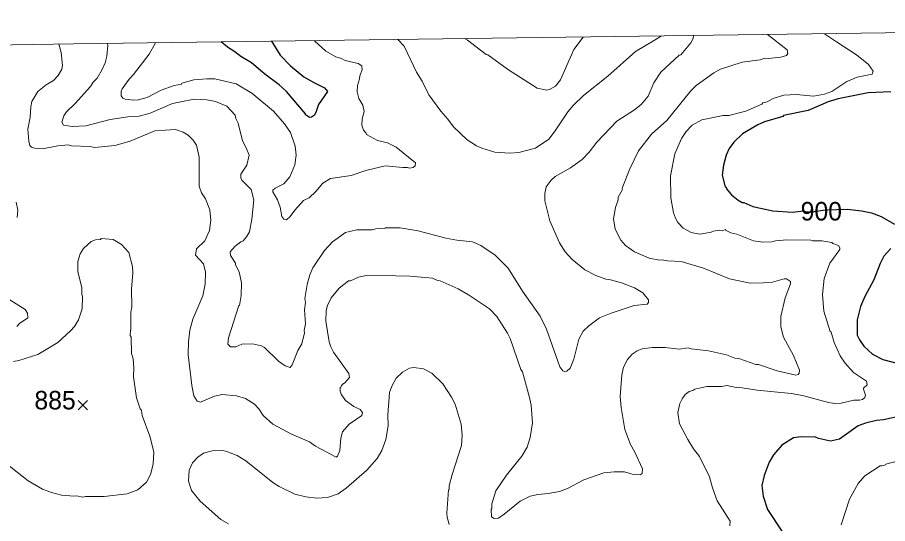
# Model space of a CAD drawing. Extents: x 265.7 to 292.1, y 7676.2 to 7704.2.
# Drawn here: x 268.132 to 271.891, y 7701.825 to 7704.012 of the extents above; entities that cross this region are included whole.
import ezdxf
from ezdxf.enums import TextEntityAlignment as Align

# ---------------------------------------------------------------- set-up
doc = ezdxf.new("R2010")
doc.units = 0
doc.header["$LTSCALE"] = 0.032
for name, color, linetype, lineweight in [('1', 7, 'Continuous', 25), ('2', 7, 'Continuous', 13), ('21', 7, 'Continuous', 25), ('63', 7, 'Continuous', 25)]:
    doc.layers.add(name, color=color, linetype=linetype, lineweight=lineweight)
doc.layers.add('61', color=7, linetype='Continuous')

msp = doc.modelspace()

# ---------------------------------------------------------------- linework, layer by layer
at = {"layer": '1'}
for points in [[(269.2297, 7703.9091), (269.2666, 7703.8496), (269.3113, 7703.8033), (269.3687, 7703.7554), (269.4158, 7703.7291), (269.4589, 7703.7083), (269.4709, 7703.6924), (269.4326, 7703.6357), (269.423, 7703.6054), (269.415, 7703.5903), (269.4031, 7703.5807), (269.3935, 7703.5799), (269.3759, 7703.5918), (269.3759, 7703.5958), (269.2945, 7703.6916), (269.2626, 7703.7211), (269.2004, 7703.7674), (269.1429, 7703.8153), (269.0966, 7703.844), (269.0719, 7703.8639), (269.0388, 7703.8839), (269.0118, 7703.9061)], [(271.9055, 7703.6908), (271.8065, 7703.6868), (271.6773, 7703.6605), (271.6342, 7703.6477), (271.548, 7703.6094), (271.4411, 7703.5886), (271.4387, 7703.5847), (271.3597, 7703.5615), (271.3309, 7703.5488), (271.2639, 7703.5088), (271.2264, 7703.4737), (271.2072, 7703.4458), (271.1937, 7703.4171), (271.1817, 7703.374), (271.1769, 7703.3309), (271.1897, 7703.2798), (271.1937, 7703.2783), (271.1953, 7703.2711), (271.2168, 7703.2463), (271.2456, 7703.2224), (271.2623, 7703.2128), (271.2703, 7703.212), (271.3086, 7703.1953), (271.3948, 7703.1769), (271.481, 7703.1713), (271.528, 7703.1761), (271.54, 7703.1729), (271.5645, 7703.1728), (271.623, 7703.1804), (271.7172, 7703.1842), (271.7778, 7703.1769), (271.8209, 7703.1673), (271.864, 7703.1522), (271.9214, 7703.1194)], [(271.9047, 7703.0133), (271.8751, 7702.9806), (271.8584, 7702.9495), (271.8312, 7702.8777), (271.7929, 7702.8059), (271.7746, 7702.7628), (271.7594, 7702.7053), (271.7602, 7702.6399), (271.7698, 7702.6191), (271.789, 7702.592), (271.8257, 7702.5569), (271.8704, 7702.5337), (271.9422, 7702.5154)], [(271.9533, 7702.2912), (271.8736, 7702.2736), (271.8432, 7702.2712), (271.7954, 7702.2592), (271.7634, 7702.2473), (271.6836, 7702.1906), (271.6445, 7702.1818), (271.5927, 7702.193), (271.5791, 7702.1986), (271.5177, 7702.2002), (271.4841, 7702.1962), (271.4347, 7702.1643), (271.398, 7702.122), (271.3788, 7702.0909), (271.3573, 7702.0334), (271.3485, 7701.9903), (271.3533, 7701.9441), (271.3724, 7701.8866), (271.4347, 7701.7925), (271.4426, 7701.7518), (271.4347, 7701.7302), (271.4044, 7701.7126), (271.3756, 7701.7031), (271.3038, 7701.6903)]]:
    msp.add_lwpolyline(points, dxfattribs=at)
at = {"layer": '2'}
for points in [[(270.9148, 7703.9322), (270.8873, 7703.915), (270.8027, 7703.8647), (270.683, 7703.7586), (270.5777, 7703.6748), (270.5338, 7703.6333), (270.5098, 7703.6046), (270.4556, 7703.5224), (270.4276, 7703.4857), (270.3702, 7703.4474), (270.2984, 7703.4283), (270.2585, 7703.4251), (270.1946, 7703.4299), (270.1388, 7703.4466), (270.1148, 7703.4578), (270.0749, 7703.4833), (270.0159, 7703.54), (269.992, 7703.5727), (269.9608, 7703.607), (269.9098, 7703.6772), (269.8802, 7703.7363), (269.8555, 7703.7762), (269.802, 7703.8879), (269.7758, 7703.9166)], [(270.0631, 7703.9206), (270.0765, 7703.9134), (270.1571, 7703.852), (270.1643, 7703.8504), (270.2489, 7703.7881), (270.3766, 7703.7068), (270.4197, 7703.698), (270.434, 7703.702), (270.4564, 7703.7147), (270.4779, 7703.7427), (270.5362, 7703.8735), (270.5753, 7703.9276)], [(270.5753, 7702.6566), (270.6, 7702.6798), (270.6471, 7702.7141), (270.6974, 7702.7348), (270.7963, 7702.7668), (270.8522, 7702.7739), (270.8577, 7702.7803), (270.8577, 7702.7915), (270.8338, 7702.8218), (270.7979, 7702.8442), (270.742, 7702.8657), (270.6942, 7702.8785), (270.6742, 7702.8809), (270.6303, 7702.8976), (270.5825, 7702.9216), (270.5266, 7702.9678), (270.4987, 7702.999), (270.4731, 7703.0389), (270.4316, 7703.133), (270.4101, 7703.22), (270.4109, 7703.2511), (270.4165, 7703.2799), (270.4372, 7703.3086), (270.4548, 7703.3253), (270.5218, 7703.3628), (270.5713, 7703.3979), (270.6016, 7703.4299), (270.6351, 7703.4738), (270.7213, 7703.5639), (270.7971, 7703.6126), (270.8274, 7703.6373), (270.8561, 7703.6724), (270.8817, 7703.7299), (270.9112, 7703.7762), (270.9902, 7703.8488), (270.9974, 7703.8512), (271.0413, 7703.9023), (271.0508, 7703.9214), (271.0521, 7703.9341)], [(271.6549, 7703.0349), (271.6501, 7703.0397), (271.607, 7703.0476), (271.5671, 7703.0476), (271.5592, 7703.05), (271.4554, 7703.0516), (271.4075, 7703.0476), (271.3916, 7703.0429), (271.3517, 7703.0413), (271.3118, 7703.0476), (271.24, 7703.0764), (271.2144, 7703.0812), (271.1913, 7703.0923), (271.1905, 7703.0955), (271.1761, 7703.0907), (271.1666, 7703.0931), (271.1378, 7703.0891), (271.1283, 7703.0843), (271.0804, 7703.0756), (271.0421, 7703.0827), (271.0086, 7703.1019), (270.9854, 7703.1266), (270.975, 7703.1442), (270.9663, 7703.1681), (270.9543, 7703.232), (270.9535, 7703.3277), (270.9718, 7703.4235), (271.0014, 7703.4889), (271.0213, 7703.5192), (271.0469, 7703.5464), (271.0884, 7703.5695), (271.1809, 7703.5887), (271.2049, 7703.5887), (271.2783, 7703.6078), (271.3477, 7703.6373), (271.3517, 7703.6429), (271.3708, 7703.6477), (271.3964, 7703.6613), (271.4427, 7703.6756), (271.4969, 7703.6788), (271.5703, 7703.6724), (271.6182, 7703.6812), (271.6501, 7703.6924), (271.7148, 7703.7355), (271.7602, 7703.7546), (271.8249, 7703.7674), (271.8281, 7703.7802), (271.8089, 7703.8089), (271.757, 7703.8504), (271.6709, 7703.9062), (271.6179, 7703.9417)], [(271.141, 7703.773), (271.1698, 7703.7881), (271.2623, 7703.8185), (271.3405, 7703.8296), (271.3565, 7703.8344), (271.3629, 7703.8328), (271.4299, 7703.84), (271.4546, 7703.848), (271.4602, 7703.8568), (271.457, 7703.8727), (271.3727, 7703.9384)], [(268.3103, 7703.8965), (268.321, 7703.86), (268.3266, 7703.8049), (268.3242, 7703.7881), (268.3075, 7703.7618), (268.2875, 7703.7403), (268.2556, 7703.7203), (268.2197, 7703.6916), (268.1941, 7703.6485), (268.1894, 7703.6262), (268.187, 7703.5815), (268.1774, 7703.5288), (268.1806, 7703.4777), (268.1854, 7703.4586), (268.1926, 7703.4514), (268.2061, 7703.4466), (268.2396, 7703.4442), (268.3067, 7703.4578), (268.3514, 7703.461), (268.3649, 7703.4578), (268.4455, 7703.4546), (268.4663, 7703.4506), (268.5524, 7703.4594), (268.6195, 7703.4777), (268.7256, 7703.5224), (268.8142, 7703.528), (268.8477, 7703.5168), (268.87, 7703.5041), (268.8908, 7703.4825), (268.9059, 7703.4602), (268.9171, 7703.4091), (268.9171, 7703.283), (268.9267, 7703.2543), (268.9442, 7703.228), (268.9626, 7703.1809), (268.9682, 7703.1362), (268.9618, 7703.0915), (268.9418, 7703.0468), (268.9051, 7703.0125), (268.9019, 7702.9854), (268.9355, 7702.9479), (268.945, 7702.9112), (268.9426, 7702.8601), (268.9323, 7702.809), (268.89, 7702.7085), (268.8764, 7702.6606), (268.8708, 7702.6112), (268.87, 7702.5553), (268.8852, 7702.4212), (268.894, 7702.3766), (268.9083, 7702.3542), (268.9235, 7702.3494), (268.9833, 7702.3758), (269.0169, 7702.3829), (269.0791, 7702.3774), (269.1174, 7702.3662), (269.1557, 7702.3414), (269.1748, 7702.3207), (269.1932, 7702.292), (269.2347, 7702.2545), (269.3153, 7702.2114), (269.3935, 7702.1787), (269.419, 7702.1603), (269.5084, 7702.1116), (269.5148, 7702.1172), (269.5251, 7702.1404), (269.5291, 7702.1946), (269.5363, 7702.2217), (269.5658, 7702.2545), (269.6193, 7702.292), (269.6225, 7702.3055), (269.6129, 7702.3183), (269.585, 7702.3311), (269.5491, 7702.3566), (269.5299, 7702.3837), (269.5259, 7702.3973), (269.5259, 7702.4133), (269.5307, 7702.4157), (269.5323, 7702.422), (269.5403, 7702.4308), (269.5451, 7702.4316), (269.5666, 7702.4571), (269.5642, 7702.4731), (269.4972, 7702.5665), (269.4852, 7702.5888), (269.4781, 7702.6112), (269.4645, 7702.7005), (269.4661, 7702.7452), (269.4717, 7702.7676), (269.4876, 7702.8011), (269.522, 7702.8418), (269.5627, 7702.8737), (269.5714, 7702.8745), (269.6057, 7702.8904), (269.6393, 7702.8976)], [(268.5209, 7703.8994), (268.5221, 7703.8911), (268.5189, 7703.8448), (268.5109, 7703.8161), (268.4982, 7703.7874), (268.4758, 7703.7498), (268.4591, 7703.7323), (268.4471, 7703.7139), (268.3809, 7703.6405), (268.3434, 7703.6038), (268.3322, 7703.5863), (268.3234, 7703.5591), (268.3306, 7703.5472), (268.3689, 7703.5416), (268.428, 7703.544), (268.5333, 7703.5711), (268.6195, 7703.5847), (268.6578, 7703.5855), (268.7056, 7703.5982), (268.8022, 7703.6397), (268.8956, 7703.6589), (268.9498, 7703.6565), (268.9881, 7703.6485), (269.036, 7703.6286), (269.0727, 7703.5903), (269.0759, 7703.5759), (269.0863, 7703.5559), (269.1038, 7703.4793), (269.1206, 7703.449), (269.1333, 7703.4171), (269.123, 7703.374), (269.0966, 7703.3349), (269.0966, 7703.3197), (269.1014, 7703.3094), (269.1413, 7703.2687), (269.1533, 7703.224), (269.1453, 7703.141), (269.1349, 7703.0859), (269.1222, 7703.0644), (269.1078, 7703.0476), (269.0966, 7703.0429), (269.0711, 7703.0229), (269.0512, 7702.9998), (269.0528, 7702.9838), (269.0735, 7702.9511), (269.0743, 7702.9439), (269.0903, 7702.9128), (269.1006, 7702.8649), (269.099, 7702.8107), (269.0919, 7702.7676), (269.0887, 7702.7668), (269.0432, 7702.6271), (269.0408, 7702.6), (269.0527, 7702.5888), (269.0759, 7702.5896), (269.1014, 7702.6), (269.1477, 7702.6024), (269.186, 7702.5928), (269.1996, 7702.5864), (269.2594, 7702.5266), (269.289, 7702.5066), (269.3105, 7702.4994), (269.3185, 7702.5106), (269.3432, 7702.5729), (269.36, 7702.6016), (269.3727, 7702.6495), (269.3711, 7702.659), (269.3759, 7702.6878), (269.3727, 7702.7484), (269.3759, 7702.7803), (269.3743, 7702.7979), (269.3839, 7702.8585), (269.3959, 7702.9), (269.4086, 7702.9303), (269.4589, 7703.0054), (269.4924, 7703.0421), (269.5499, 7703.0827), (269.5978, 7703.0939), (269.6648, 7703.0939), (269.6808, 7703.0987), (269.7207, 7703.1011), (269.7222, 7703.1035), (269.7861, 7703.1035), (269.8627, 7703.0907), (269.9824, 7703.0588), (270.0303, 7703.0492), (270.0973, 7703.0429), (270.134, 7703.0269), (270.1954, 7702.9846), (270.2521, 7702.9287), (270.3135, 7702.829), (270.3901, 7702.7213), (270.4173, 7702.6654), (270.4755, 7702.5026), (270.4875, 7702.4859)], [(269.4158, 7703.9117), (269.4645, 7703.8663), (269.5068, 7703.8424), (269.5323, 7703.8344), (269.5483, 7703.8256), (269.6041, 7703.8137), (269.6201, 7703.8025), (269.6217, 7703.7858), (269.6105, 7703.7602), (269.6097, 7703.7475), (269.6009, 7703.7187), (269.6002, 7703.69), (269.6073, 7703.6613), (269.6241, 7703.6326), (269.6305, 7703.6054), (269.6209, 7703.5735), (269.6201, 7703.5464), (269.6273, 7703.5248), (269.6385, 7703.5121), (269.6401, 7703.5057), (269.6871, 7703.4809), (269.7302, 7703.4706), (269.7685, 7703.4522), (269.8515, 7703.3836), (269.8507, 7703.3708), (269.8411, 7703.3636), (269.826, 7703.3612), (269.8164, 7703.3644), (269.7973, 7703.3636), (269.7207, 7703.3708), (269.6377, 7703.3509), (269.5738, 7703.3285), (269.4845, 7703.3158), (269.4517, 7703.2958), (269.4214, 7703.2599), (269.3919, 7703.2328), (269.368, 7703.2216), (269.3304, 7703.1801), (269.3105, 7703.1514), (269.2937, 7703.1378), (269.2834, 7703.1402), (269.2746, 7703.1522), (269.2674, 7703.1921), (269.2562, 7703.224), (269.2355, 7703.2591), (269.2355, 7703.2655), (269.2451, 7703.2751), (269.2834, 7703.2926), (269.3081, 7703.3229), (269.3304, 7703.3756), (269.336, 7703.4171), (269.332, 7703.4554), (269.3121, 7703.5144), (269.2858, 7703.552), (269.2387, 7703.607), (269.1445, 7703.6852), (269.0775, 7703.7251), (268.9849, 7703.7475), (268.9498, 7703.7474), (268.894, 7703.7419), (268.8429, 7703.7275), (268.8413, 7703.7243), (268.8094, 7703.7179), (268.7535, 7703.6972), (268.6929, 7703.6669), (268.6546, 7703.6565), (268.6354, 7703.6549), (268.5971, 7703.6589), (268.5875, 7703.6629), (268.5796, 7703.6732), (268.5796, 7703.6916), (268.5843, 7703.7036), (268.6147, 7703.7459), (268.633, 7703.765), (268.7009, 7703.8528), (268.7283, 7703.9023)], [(270.7771, 7703.3581), (270.8154, 7703.4363), (270.8713, 7703.5081), (270.9367, 7703.5671), (271.0405, 7703.6948), (271.0636, 7703.7179), (271.141, 7703.773)], [(269.9584, 7702.8737), (270.0366, 7702.8394), (270.0813, 7702.813), (270.1707, 7702.7524), (270.2026, 7702.7205), (270.2497, 7702.6479), (270.2601, 7702.6255), (270.3071, 7702.4915), (270.3143, 7702.4803), (270.3447, 7702.3702), (270.351, 7702.3367), (270.3566, 7702.2601), (270.347, 7702.197), (270.3335, 7702.1547), (270.3111, 7702.1164), (270.2441, 7702.035), (270.1994, 7701.9664), (270.1819, 7701.9105), (270.1819, 7701.8906), (270.1779, 7701.8866), (270.1795, 7701.8539), (270.1914, 7701.8475), (270.2098, 7701.8491), (270.2353, 7701.8659), (270.3032, 7701.9217), (270.3471, 7701.9433), (270.3798, 7701.9512), (270.4245, 7701.9552), (270.4739, 7701.964), (270.509, 7701.9768), (270.5793, 7702.0143), (270.6654, 7702.0438), (270.7101, 7702.0494), (270.7548, 7702.0486), (270.7883, 7702.0382), (270.8218, 7702.0358), (270.8306, 7702.0422), (270.833, 7702.0622), (270.7995, 7702.134), (270.7803, 7702.1675), (270.7564, 7702.2313), (270.7396, 7702.3271), (270.7365, 7702.375), (270.7428, 7702.4675), (270.75, 7702.501), (270.7676, 7702.5346), (270.7883, 7702.5569), (270.8091, 7702.5721), (270.8314, 7702.58), (270.8761, 7702.5856), (270.9304, 7702.5864), (270.991, 7702.5792), (271.0293, 7702.584), (271.0421, 7702.58), (271.1171, 7702.5721), (271.1953, 7702.5545), (271.2312, 7702.5401), (271.2479, 7702.5385), (271.3222, 7702.513), (271.3333, 7702.513), (271.4139, 7702.4851), (271.4953, 7702.4659), (271.5041, 7702.4691), (271.5089, 7702.4755), (271.5105, 7702.4883), (271.4841, 7702.5521), (271.441, 7702.6303), (271.4299, 7702.675), (271.4299, 7702.7197), (271.449, 7702.8011), (271.4714, 7702.8617), (271.4714, 7702.8713), (271.4546, 7702.8825), (271.4442, 7702.8825), (271.3932, 7702.8689), (271.3549, 7702.8649), (271.2974, 7702.8641), (271.2081, 7702.8833), (271.0963, 7702.9295), (270.9998, 7702.9583), (270.9399, 7702.9599), (270.9176, 7702.9647), (270.9064, 7702.9631), (270.8617, 7702.9718), (270.7979, 7702.9998), (270.7588, 7703.0269), (270.7388, 7703.05), (270.7141, 7703.0979), (270.7069, 7703.1426), (270.7157, 7703.1905), (270.7269, 7703.224), (270.7269, 7703.2352), (270.7452, 7703.2687), (270.7444, 7703.2743), (270.7771, 7703.3581)], [(268.1271, 7703.2136), (268.1343, 7703.1793), (268.1303, 7703.1474)], [(268.0266, 7702.1284), (268.179, 7702.0095), (268.2404, 7701.9736), (268.2795, 7701.9592), (268.3226, 7701.948), (268.3753, 7701.9433), (268.3873, 7701.9449), (268.4152, 7701.9393), (268.4264, 7701.9425), (268.5062, 7701.9417), (268.6067, 7701.9544), (268.6522, 7701.9704), (268.6897, 7702.0047), (268.7064, 7702.0366), (268.7184, 7702.0813), (268.7216, 7702.1356), (268.704, 7702.2026), (268.6713, 7702.292), (268.6673, 7702.3151), (268.6618, 7702.3207), (268.6466, 7702.3686), (268.633, 7702.4595), (268.6346, 7702.4986), (268.6314, 7702.5377), (268.625, 7702.5601), (268.6227, 7702.6311), (268.6195, 7702.6383), (268.6203, 7702.6606), (268.6226, 7702.6614), (268.6226, 7702.7388), (268.6258, 7702.7612), (268.625, 7702.8378), (268.6306, 7702.908), (268.629, 7702.9367), (268.6131, 7702.9966), (268.5812, 7703.0317), (268.5453, 7703.0524), (268.4934, 7703.0564), (268.491, 7703.0532), (268.4694, 7703.0508), (268.4503, 7703.0444), (268.4168, 7703.0141), (268.4024, 7702.9902), (268.3936, 7702.9575), (268.3928, 7702.9144), (268.4104, 7702.8434), (268.4104, 7702.8154), (268.4136, 7702.8059), (268.4112, 7702.7532), (268.396, 7702.7053), (268.3785, 7702.6766), (268.3617, 7702.6574), (268.3067, 7702.6072), (268.2205, 7702.5561), (268.1374, 7702.5292), (268.1144, 7702.5258)], [(271.6102, 7702.8154), (271.6174, 7702.8841), (271.6421, 7702.9511), (271.6844, 7703.0101), (271.6844, 7703.0173), (271.6796, 7703.0261), (271.6549, 7703.0349)], [(269.6393, 7702.8976), (269.7414, 7702.8992), (269.7669, 7702.8952), (269.8276, 7702.8944), (269.9249, 7702.8849), (269.9473, 7702.8753), (269.9584, 7702.8737)], [(268.0609, 7702.8162), (268.1654, 7702.75), (268.1758, 7702.734), (268.1766, 7702.7149), (268.1407, 7702.6902), (268.1295, 7702.6774)], [(271.2096, 7701.8156), (271.2104, 7701.8355), (271.1554, 7701.9233), (271.1346, 7701.9792), (271.1219, 7702.0271), (271.0788, 7702.1148), (271.0524, 7702.1483), (271.0277, 7702.1882), (270.9918, 7702.2569), (270.9854, 7702.3047), (270.9942, 7702.3446), (271.003, 7702.3638), (271.0165, 7702.3829), (271.0333, 7702.3965), (271.0501, 7702.4005), (271.058, 7702.4061), (271.1107, 7702.4172), (271.1745, 7702.418), (271.1969, 7702.422), (271.2368, 7702.4125), (271.2448, 7702.4141), (271.3277, 7702.4013), (271.4746, 7702.3869), (271.524, 7702.3789), (271.6358, 7702.3486), (271.6629, 7702.3446), (271.69, 7702.3454), (271.7459, 7702.3582), (271.7698, 7702.3582), (271.7834, 7702.3614), (271.7922, 7702.3694), (271.7961, 7702.3805), (271.7866, 7702.4053), (271.7874, 7702.4101), (271.8025, 7702.4252), (271.8001, 7702.4404), (271.7443, 7702.4787), (271.7076, 7702.5186), (271.6868, 7702.5497), (271.6605, 7702.608), (271.6469, 7702.6526), (271.6429, 7702.6558), (271.6158, 7702.7436), (271.6102, 7702.8154)], [(270.4875, 7702.4859), (270.4947, 7702.4819), (270.5058, 7702.4835), (270.5194, 7702.4962), (270.5362, 7702.5362), (270.5577, 7702.6223), (270.5753, 7702.6566)], [(269.7334, 7702.2473), (269.7318, 7702.2952), (269.7398, 7702.3909), (269.7494, 7702.4196), (269.7685, 7702.4532), (269.7949, 7702.4795), (269.826, 7702.4962), (269.8451, 7702.4994), (269.8858, 7702.4939), (269.9217, 7702.4755), (269.9704, 7702.4292), (270.0079, 7702.3718), (270.0223, 7702.3414), (270.0494, 7702.2553), (270.0526, 7702.2074), (270.0502, 7702.1627), (270.0095, 7702.0366), (269.9975, 7701.9887), (269.9975, 7701.9728), (269.9943, 7701.9712), (269.9872, 7701.8707), (269.9888, 7701.8531), (269.9975, 7701.8212)], [(269.518, 7701.9544), (269.5523, 7701.9784), (269.6409, 7702.0558), (269.6863, 7702.1068), (269.7063, 7702.1404), (269.7238, 7702.1882), (269.7334, 7702.2473)], [(269.0432, 7701.8244), (269.0113, 7701.8435), (268.9211, 7701.9217), (268.8844, 7701.968), (268.8708, 7702.0079), (268.8732, 7702.0558), (268.8876, 7702.0877), (268.9107, 7702.1124), (268.9355, 7702.1292), (268.9738, 7702.1396), (269.0169, 7702.1412), (269.0328, 7702.138), (269.0807, 7702.1188), (269.119, 7702.0957), (269.2347, 7702.0023), (269.2634, 7701.9848), (269.3297, 7701.9528), (269.3775, 7701.9401), (269.4254, 7701.9345), (269.4717, 7701.9385), (269.518, 7701.9544)], [(271.69, 7701.8196), (271.7259, 7701.9313), (271.7634, 7701.9983), (271.7922, 7702.031), (271.8584, 7702.0749), (271.8672, 7702.0741), (271.8823, 7702.0789), (271.8831, 7702.0821), (271.9717, 7702.1044)]]:
    msp.add_lwpolyline(points, dxfattribs=at)
at = {"layer": '21'}
for p, q in [((268.3937, 7702.3576), (268.4349, 7702.3164)), ((268.4349, 7702.3576), (268.3937, 7702.3164))]:
    msp.add_line(p, q, dxfattribs=at)
at = {"layer": '63', "lineweight": 13}
msp.add_lwpolyline([(265.7179, 7703.8606), (266.2494, 7703.868), (266.7808, 7703.8754), (267.3123, 7703.8828), (267.8437, 7703.8901), (268.3752, 7703.8974), (268.9066, 7703.9047), (269.4381, 7703.912), (269.9695, 7703.9193), (270.501, 7703.9265), (271.0324, 7703.9338), (271.5639, 7703.941), (272.0953, 7703.9482), (272.6268, 7703.9554), (273.1582, 7703.9626), (273.6896, 7703.9697), (274.2211, 7703.9769), (274.7525, 7703.984), (275.2839, 7703.9911), (275.8154, 7703.9982), (276.3468, 7704.0052), (276.8782, 7704.0123)], dxfattribs=at)

# ---------------------------------------------------------------- texts
at = {"layer": '61'}
for s, p in [('900', (271.6048, 7703.1348)), ('885', (268.2946, 7702.3184))]:
    msp.add_text(s, height=0.08, dxfattribs=at).set_placement(p, align=Align.CENTER)

doc.saveas('drawing.dxf')
